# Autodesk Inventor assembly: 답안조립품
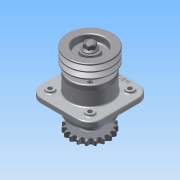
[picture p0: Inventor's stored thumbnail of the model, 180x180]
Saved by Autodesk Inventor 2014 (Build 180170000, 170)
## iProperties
Created: 2015-09
Part Number: 답안조립품
Document SubType Name: Assembly
Designer: study
Author: study
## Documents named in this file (12)
- C:\Users\study\Desktop\450909V1003\답안조립품.iam
- C:\Users\study\Desktop\450909V1003\1-본체.ipt
- C:\Users\study\Desktop\450909V1003\6-베어링 6206.ipt
- C:\Users\study\Desktop\450909V1003\8-오일실 30x42.ipt
- C:\Users\study\Desktop\450909V1003\2-커버.ipt
- C:\Users\study\Desktop\450909V1003\3-축.ipt
- C:\Users\study\Desktop\450909V1003\11-키 6x6.ipt
- C:\Users\study\Desktop\450909V1003\10-M6.ipt
- C:\Users\study\Desktop\450909V1003\4-V벨트풀리.ipt
- C:\Users\study\Desktop\450909V1003\5-체인 스프로킷.ipt
- C:\Users\study\Desktop\450909V1003\7-부시.ipt
- C:\Users\study\Desktop\450909V1003\9-M16-너트.ipt
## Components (23 placed, 11 different names)
1. 1-본체:1
2. 6-베어링 6206:1
3. 6-베어링 6206:2
4. 8-8-오일실 30x42:1
5. 8-8-오일실 30x42:2
6. 2-커버:1
7. 2-커버:2
8. 3-축:1 — 각도:1, 각도:2
9. 11-키 6x6:1 — 각도:2, 각도:4
10. 11-키 6x6:2 — 각도:1, 각도:3
11. 4-V벨트풀리:1 — 각도:3
12. 5-체인 스프로킷:1 — 각도:4
13. 7-부시:1
14. 9-M16 너트:1
15. 9-M16 너트:2
16. 10-M6:2
17. 10-M6:3
18. 10-M6:4
19. 10-M6:5
20. 10-M6:1
21. 10-M6:6
22. 10-M6:7
23. 10-M6:8
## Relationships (4: Angle 4)
- 각도:1 [Angle]: 3-축:1 ↔ 11-키 6x6:2
- 각도:2 [Angle]: 3-축:1 ↔ 11-키 6x6:1
- 각도:3 [Angle]: 11-키 6x6:2 ↔ 4-V벨트풀리:1
- 각도:4 [Angle]: 11-키 6x6:1 ↔ 5-체인 스프로킷:1
